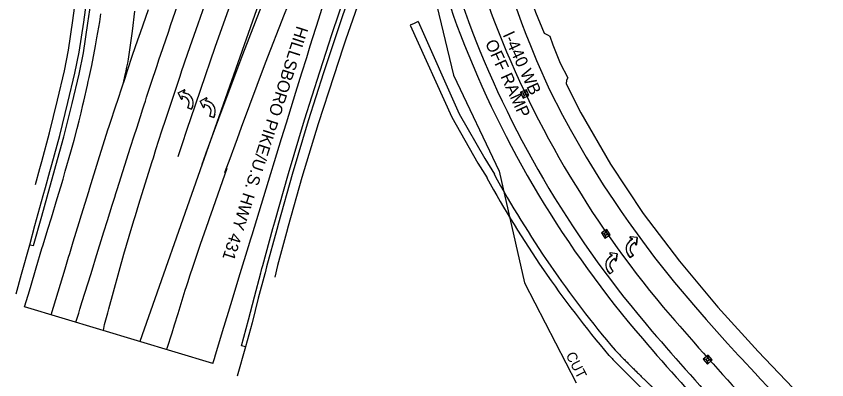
# Model space of a CAD drawing. Extents: x 1730210 to 1732101, y 650763 to 653427.
# Drawn here: x 1730314.4 to 1730714.9, y 652609 to 652788.8 of the extents above; entities that cross this region are included whole.
import ezdxf

# ---------------------------------------------------------------- set-up
doc = ezdxf.new("R2010")
doc.units = 0
for name, color, linetype in [('DESIGN - DRAINAGE - Special Ditches', 7, 'Continuous'), ('DESIGN - ROW - Slope Lines', 7, 'Continuous'), ('DESIGN - ROW - Slope Lines Text', 7, 'Continuous'), ('DESIGN - SCRATCH - User 2', 7, 'Continuous'), ('DESIGN - TRAFFIC CONTROL PERMANENT - Pavement Marking', 7, 'Continuous'), ('DESIGN - TRANSPORTATION - Edge of Traveled Way', 7, 'Continuous'), ('DESIGN - TRANSPORTATION - Intersection Lines', 7, 'Continuous'), ('DESIGN - TRANSPORTATION - Shoulder Lines', 7, 'Continuous'), ('SURVEY - DRAINAGE - Pipes and Culverts', 7, 'Continuous'), ('SURVEY - TRANSPORTATION - Features', 7, 'Continuous'), ('SURVEY - TRANSPORTATION - Roads Text', 7, 'Continuous')]:
    doc.layers.add(name, color=color, linetype=linetype)

msp = doc.modelspace()

# ---------------------------------------------------------------- linework, layer by layer
at = {"layer": 'DESIGN - DRAINAGE - Special Ditches'}
for radius in [533, 529]:
    msp.add_arc((1731014.28, 652965.13), radius, 208.7383, 220.1975, dxfattribs=at)
for points in [[(1730610.11, 652623.81), (1730622.09, 652611.66), (1730634.46, 652599.88), (1730646.95, 652588.22)], [(1730607.26, 652621), (1730619.3, 652608.79), (1730631.71, 652596.98), (1730644.22, 652585.3)]]:
    msp.add_open_spline(points, degree=2, dxfattribs=at)
at = {"layer": 'DESIGN - ROW - Slope Lines'}
for p, q in [((1730517.89, 652812.05), (1730530.41, 652759.65)), ((1730530.41, 652759.65), (1730553, 652712.18)), ((1730553, 652712.18), (1730565.43, 652657.01)), ((1730565.43, 652657.01), (1730591, 652607.46))]:
    msp.add_line(p, q, dxfattribs=at)
at = {"layer": 'DESIGN - SCRATCH - User 2'}
msp.add_lwpolyline([(1730561.33, 652793.06), (1730564.07, 652785.56), (1730566.16, 652779.94), (1730568.4, 652774.39), (1730571.4, 652766.99), (1730577.92, 652752.4), (1730584.31, 652739.97), (1730588.01, 652732.9), (1730595.99, 652719.05), (1730604.38, 652705.46), (1730609.95, 652697.18), (1730613.29, 652692.21), (1730616.72, 652687.3), (1730623.79, 652677.63), (1730629.7, 652669.58), (1730639.65, 652657.09), (1730649.97, 652644.9), (1730655.19, 652638.85), (1730664.52, 652628.44), (1730665.85, 652626.95), (1730671.28, 652621.1), (1730672.64, 652619.64), (1730679.45, 652612.34), (1730682.18, 652609.42), (1730689.03, 652602.15)], dxfattribs=at)
at = {"layer": 'DESIGN - TRAFFIC CONTROL PERMANENT - Pavement Marking'}
for p, q in [((1730454.87, 652854.32), (1730406.19, 652715.68)), ((1730394.35, 652750.93), (1730397.36, 652752.46)), ((1730394.35, 652750.93), (1730397.36, 652752.46)), ((1730397.66, 652752.08), (1730396.86, 652751.15)), ((1730396.86, 652751.15), (1730397.66, 652752.08)), ((1730396.86, 652751.15), (1730398.4, 652750.65)), ((1730398.4, 652750.65), (1730396.86, 652751.15)), ((1730395.89, 652747.92), (1730394.35, 652750.93)), ((1730394.35, 652750.93), (1730395.89, 652747.92)), ((1730397.79, 652748.78), (1730396.26, 652749.28)), ((1730396.26, 652749.28), (1730396.35, 652748.05)), ((1730397.79, 652748.78), (1730396.26, 652749.28)), ((1730396.26, 652749.28), (1730396.35, 652748.05)), ((1730405.27, 652746.88), (1730408.27, 652748.42)), ((1730405.27, 652746.88), (1730408.27, 652748.42)), ((1730408.57, 652748.04), (1730407.78, 652747.11)), ((1730407.78, 652747.11), (1730408.57, 652748.04)), ((1730407.78, 652747.11), (1730409.32, 652746.61)), ((1730409.32, 652746.61), (1730407.78, 652747.11)), ((1730399.18, 652743.47), (1730399.69, 652745.06)), ((1730399.18, 652743.47), (1730399.69, 652745.06)), ((1730401.05, 652742.86), (1730399.18, 652743.47)), ((1730399.18, 652743.47), (1730401.05, 652742.86)), ((1730401.57, 652744.46), (1730401.05, 652742.86)), ((1730401.05, 652742.86), (1730401.57, 652744.46)), ((1730406.8, 652743.88), (1730405.27, 652746.88)), ((1730405.27, 652746.88), (1730406.8, 652743.88)), ((1730408.71, 652744.74), (1730407.17, 652745.23)), ((1730407.17, 652745.23), (1730407.27, 652744.01)), ((1730408.71, 652744.74), (1730407.17, 652745.23)), ((1730407.17, 652745.23), (1730407.27, 652744.01)), ((1730410.09, 652739.43), (1730410.61, 652741.02)), ((1730410.09, 652739.43), (1730410.61, 652741.02)), ((1730411.97, 652738.82), (1730410.09, 652739.43)), ((1730410.09, 652739.43), (1730411.97, 652738.82)), ((1730412.48, 652740.41), (1730411.97, 652738.82)), ((1730411.97, 652738.82), (1730412.48, 652740.41)), ((1730406.19, 652715.68), (1730375.39, 652627.97)), ((1730617.71, 652679.28), (1730618.79, 652678.68)), ((1730618.79, 652678.68), (1730617.71, 652679.28)), ((1730621.22, 652679.35), (1730617.86, 652679.74)), ((1730621.22, 652679.35), (1730617.86, 652679.74)), ((1730620.83, 652676), (1730621.22, 652679.35)), ((1730621.22, 652679.35), (1730620.83, 652676)), ((1730618.79, 652678.68), (1730617.52, 652677.67)), ((1730617.52, 652677.67), (1730618.79, 652678.68)), ((1730618.75, 652676.13), (1730620.01, 652677.14)), ((1730618.75, 652676.13), (1730620.01, 652677.14)), ((1730620.01, 652677.14), (1730620.35, 652675.96)), ((1730620.01, 652677.14), (1730620.35, 652675.96)), ((1730607.7, 652671.31), (1730608.78, 652670.72)), ((1730608.78, 652670.72), (1730607.7, 652671.31)), ((1730611.21, 652671.39), (1730607.85, 652671.77)), ((1730611.21, 652671.39), (1730607.85, 652671.77)), ((1730610.82, 652668.03), (1730611.21, 652671.39)), ((1730611.21, 652671.39), (1730610.82, 652668.03)), ((1730619.31, 652670.67), (1730618.27, 652671.99)), ((1730619.31, 652670.67), (1730618.27, 652671.99)), ((1730608.78, 652670.72), (1730607.51, 652669.71)), ((1730607.51, 652669.71), (1730608.78, 652670.72)), ((1730608.74, 652668.17), (1730610, 652669.18)), ((1730608.74, 652668.17), (1730610, 652669.18)), ((1730610, 652669.18), (1730610.34, 652667.99)), ((1730610, 652669.18), (1730610.34, 652667.99)), ((1730616.73, 652670.76), (1730617.77, 652669.45)), ((1730617.77, 652669.45), (1730616.73, 652670.76)), ((1730617.77, 652669.45), (1730619.31, 652670.67)), ((1730619.31, 652670.67), (1730617.77, 652669.45)), ((1730609.3, 652662.71), (1730608.26, 652664.02)), ((1730609.3, 652662.71), (1730608.26, 652664.02)), ((1730606.72, 652662.8), (1730607.76, 652661.49)), ((1730607.76, 652661.49), (1730606.72, 652662.8)), ((1730607.76, 652661.49), (1730609.3, 652662.71)), ((1730609.3, 652662.71), (1730607.76, 652661.49))]:
    msp.add_line(p, q, dxfattribs=at)
for points in [[(1730383.39, 652722.85), (1730386.34, 652732.15), (1730388.22, 652737.84), (1730395.16, 652758.69), (1730396.44, 652762.47), (1730397.08, 652764.36), (1730397.72, 652766.26), (1730400.29, 652773.82), (1730404.2, 652785.15), (1730408.8, 652798.35), (1730410.17, 652802.1), (1730411.54, 652805.86), (1730412.22, 652807.74), (1730413.58, 652811.49), (1730415.63, 652817.12), (1730417, 652820.88), (1730418.42, 652824.61), (1730420.57, 652830.2), (1730422.71, 652835.8), (1730423.43, 652837.66), (1730424.86, 652841.39), (1730426.33, 652845.1), (1730433.49, 652863.11)], [(1730394.34, 652719.4), (1730396.63, 652726.34), (1730398.51, 652732.03), (1730399.14, 652733.92), (1730400.42, 652737.7), (1730405.54, 652752.84), (1730412.73, 652773.6), (1730419.37, 652792.44), (1730420.06, 652794.32), (1730422.11, 652799.95), (1730423.48, 652803.7), (1730424.84, 652807.45), (1730426.21, 652811.21), (1730426.9, 652813.08), (1730430.4, 652822.43), (1730433.3, 652829.88), (1730442.75, 652854.07), (1730444.61, 652858.82)], [(1730406.19, 652715.68), (1730406.87, 652717.55), (1730408.25, 652721.3), (1730412.37, 652732.56), (1730414.44, 652738.18), (1730426.36, 652769.97), (1730435.72, 652794.2), (1730437.19, 652797.91), (1730438.66, 652801.63), (1730439.39, 652803.49), (1730440.86, 652807.2), (1730443.07, 652812.77), (1730444.55, 652816.48), (1730446.78, 652822.05), (1730447.52, 652823.9), (1730448.26, 652825.76), (1730451.23, 652833.18), (1730452.71, 652836.89), (1730454.94, 652842.45), (1730455.69, 652844.3), (1730459.76, 652854.48)], [(1730417.45, 652711.55), (1730418.14, 652713.43), (1730419.51, 652717.18), (1730423.63, 652728.42), (1730425.69, 652734), (1730437.58, 652765.71), (1730446.9, 652789.83), (1730448.35, 652793.51), (1730449.82, 652797.22), (1730450.55, 652799.08), (1730452.01, 652802.79), (1730454.22, 652808.33), (1730455.7, 652812.03), (1730459.4, 652821.3), (1730462.37, 652828.71), (1730463.85, 652832.42), (1730466.08, 652837.98), (1730466.83, 652839.84), (1730470.16, 652848.16)], [(1730343.84, 652637.47), (1730345.25, 652642.06), (1730345.85, 652643.97), (1730347.03, 652647.79), (1730351.18, 652661.14), (1730352.36, 652664.96), (1730353.55, 652668.77), (1730357.69, 652682.13), (1730359.48, 652687.84), (1730361.86, 652695.46), (1730363.06, 652699.28), (1730363.65, 652701.18), (1730364.25, 652703.09), (1730370.84, 652724.04), (1730372.68, 652729.74), (1730373.9, 652733.54), (1730375.74, 652739.24), (1730376.96, 652743.04), (1730377.57, 652744.94), (1730378.19, 652746.84), (1730378.8, 652748.74), (1730381.86, 652758.25), (1730383.14, 652762.03), (1730383.78, 652763.92), (1730385.06, 652767.71), (1730385.7, 652769.6), (1730386.98, 652773.38), (1730388.26, 652777.16), (1730389.54, 652780.95), (1730390.82, 652784.73), (1730394.02, 652794.19)], [(1730379.6, 652791.98), (1730378.28, 652788.22), (1730375.63, 652780.68), (1730374.97, 652778.8), (1730374.32, 652776.91), (1730371.74, 652769.35), (1730369.16, 652761.79), (1730367.98, 652757.97), (1730367.41, 652756.06), (1730367.37, 652755.91)], [(1730367.37, 652755.91), (1730368.2, 652759.82), (1730368.62, 652761.77), (1730369.04, 652763.72), (1730369.45, 652765.68), (1730369.87, 652767.63), (1730371.87, 652781.47), (1730372.99, 652791.4)], [(1730318.54, 652645.09), (1730320.26, 652650.92), (1730321.41, 652654.74), (1730324.26, 652664.32), (1730327.11, 652673.89), (1730327.69, 652675.8), (1730330.01, 652683.45), (1730331.75, 652689.18), (1730334.65, 652698.74), (1730336.4, 652704.47), (1730337.51, 652708.3), (1730338.63, 652712.13), (1730341.42, 652721.72), (1730342.98, 652727.5), (1730344.51, 652733.29), (1730345.54, 652737.15), (1730346.44, 652741.04), (1730347.32, 652744.94), (1730347.77, 652746.88), (1730349.54, 652754.67), (1730349.99, 652756.62), (1730350.43, 652758.57), (1730351.76, 652764.41), (1730353.54, 652774.24), (1730354.24, 652778.17), (1730355.62, 652786.04), (1730356.22, 652789.99)], [(1730331.64, 652641.14), (1730338.49, 652663.91), (1730340.25, 652669.64), (1730340.83, 652671.55), (1730342.59, 652677.28), (1730345.51, 652686.83), (1730346.68, 652690.65), (1730348.44, 652696.37), (1730350.2, 652702.1), (1730350.8, 652704), (1730354.94, 652717.35), (1730359.68, 652732.6), (1730360.3, 652734.5), (1730360.93, 652736.4), (1730363.43, 652743.98), (1730364.68, 652747.78), (1730366.56, 652753.46), (1730367.37, 652755.91)], [(1730566.46, 652752.5), (1730563.56, 652751.26), (1730564.81, 652748.36), (1730567.71, 652749.61), (1730566.46, 652752.5)], [(1730566.46, 652752.5), (1730565.94, 652751.19), (1730564.83, 652750.71), (1730563.56, 652751.26)], [(1730567.71, 652749.61), (1730566.39, 652750.13), (1730565.29, 652749.66), (1730564.81, 652748.36)], [(1730357.46, 652633.37), (1730358.07, 652636.39), (1730359.63, 652642.17), (1730360.16, 652644.1), (1730367.51, 652671.08), (1730371.52, 652684.48), (1730372.66, 652688.31), (1730373.24, 652690.22), (1730374.95, 652695.96), (1730379.72, 652711.21), (1730381.52, 652716.92), (1730382.12, 652718.83), (1730383.38, 652722.85)], [(1730388.8, 652623.93), (1730389.03, 652624.69), (1730391.39, 652632.32), (1730392.58, 652636.14), (1730394.35, 652641.86), (1730397.91, 652653.3), (1730398.5, 652655.21), (1730399.09, 652657.12), (1730400.34, 652660.91), (1730401.63, 652664.7), (1730405.5, 652676.04), (1730409.37, 652687.38), (1730410.02, 652689.27), (1730410.66, 652691.16), (1730418.62, 652713.77)], [(1730606.17, 652683.38), (1730603.53, 652681.66), (1730605.25, 652679.02), (1730607.89, 652680.74), (1730606.17, 652683.38)], [(1730606.17, 652683.38), (1730605.88, 652682), (1730604.87, 652681.34), (1730603.53, 652681.66)], [(1730607.89, 652680.74), (1730606.51, 652681.03), (1730605.5, 652680.38), (1730605.25, 652679.02)], [(1730656.24, 652621.26), (1730653.84, 652619.22), (1730655.88, 652616.82), (1730658.28, 652618.85), (1730656.24, 652621.26)], [(1730656.24, 652621.26), (1730656.13, 652619.85), (1730655.21, 652619.07), (1730653.84, 652619.22)], [(1730658.28, 652618.85), (1730656.87, 652618.97), (1730655.96, 652618.19), (1730655.88, 652616.82)]]:
    msp.add_lwpolyline(points, dxfattribs=at)
for points in [[(1730565.94, 652751.19), (1730566.39, 652750.13), (1730565.29, 652749.66), (1730564.83, 652750.71)], [(1730605.88, 652682), (1730606.51, 652681.03), (1730605.5, 652680.38), (1730604.87, 652681.34)], [(1730656.13, 652619.85), (1730656.87, 652618.97), (1730655.96, 652618.19), (1730655.21, 652619.07)]]:
    msp.add_lwpolyline(points, close=True, dxfattribs=at)
for centre, radius, start, end in [((1730790.39, 652878.67), 257, 184.7177, 201.1154), ((1731014.28, 652965.13), 497, 201.1154, 220.7097), ((1730397.47, 652752.24), 0.246, 319.6308, 117.079), ((1730397.47, 652752.24), 0.246, 319.6308, 117.079), ((1730396.11, 652748.03), 0.246, 207.079, 4.5722), ((1730396.11, 652748.03), 0.246, 207.079, 4.5722), ((1730396.89, 652745.97), 2.95, 342.079, 72.079), ((1730396.89, 652745.97), 2.95, 342.079, 72.079), ((1730396.89, 652745.97), 4.92, 342.079, 72.079), ((1730396.89, 652745.97), 4.92, 342.079, 72.079), ((1730408.39, 652748.2), 0.246, 319.6308, 117.079), ((1730408.39, 652748.2), 0.246, 319.6308, 117.079), ((1730407.02, 652743.99), 0.246, 207.079, 4.5722), ((1730407.02, 652743.99), 0.246, 207.079, 4.5722), ((1730407.8, 652741.93), 2.95, 342.079, 72.079), ((1730407.8, 652741.93), 2.95, 342.079, 72.079), ((1730407.8, 652741.93), 4.92, 342.079, 72.079), ((1730407.8, 652741.93), 4.92, 342.079, 72.079), ((1730617.83, 652679.49), 0.246, 83.4446, 240.8929), ((1730617.83, 652679.49), 0.246, 83.4446, 240.8929), ((1730620.58, 652673.82), 4.92, 128.4446, 218.4446), ((1730620.58, 652673.82), 4.92, 128.4446, 218.4446), ((1730620.58, 652673.82), 2.95, 128.4446, 218.4446), ((1730620.58, 652673.82), 2.95, 128.4446, 218.4446), ((1730620.59, 652676.02), 0.246, 195.9514, 353.4446), ((1730620.59, 652676.02), 0.246, 195.9514, 353.4446), ((1730607.82, 652671.53), 0.246, 83.4446, 240.8929), ((1730607.82, 652671.53), 0.246, 83.4446, 240.8929), ((1730610.57, 652665.86), 4.92, 128.4446, 218.4446), ((1730610.57, 652665.86), 4.92, 128.4446, 218.4446), ((1730610.57, 652665.86), 2.95, 128.4446, 218.4446), ((1730610.57, 652665.86), 2.95, 128.4446, 218.4446), ((1730610.58, 652668.06), 0.246, 195.9514, 353.4446), ((1730610.58, 652668.06), 0.246, 195.9514, 353.4446), ((1731772.3, 653617.35), 1497, 220.70969, 225.05905)]:
    msp.add_arc(centre, radius, start, end, dxfattribs=at)
at = {"layer": 'DESIGN - TRANSPORTATION - Edge of Traveled Way'}
for points in [[(1730470.85, 652810.26), (1730463.69, 652787.38), (1730459.51, 652774.04), (1730457.72, 652768.32), (1730455.34, 652760.69), (1730452.41, 652751.14), (1730450.06, 652743.5), (1730447.71, 652735.87), (1730445.36, 652728.23), (1730436.56, 652699.59), (1730430.73, 652680.48), (1730430.15, 652678.57), (1730428.98, 652674.75), (1730424.88, 652661.38), (1730420.21, 652646.1), (1730419.05, 652642.28), (1730416.15, 652632.72), (1730413.85, 652625.07), (1730412.7, 652621.24), (1730412.13, 652619.33), (1730411.55, 652617.42), (1730411.46, 652617.1)], [(1730561.33, 652793.06), (1730564.07, 652785.56), (1730566.16, 652779.94), (1730568.4, 652774.39), (1730571.4, 652766.99), (1730577.92, 652752.4), (1730584.31, 652739.97), (1730588.01, 652732.9), (1730595.99, 652719.05), (1730604.38, 652705.46), (1730609.95, 652697.18), (1730613.29, 652692.21), (1730616.72, 652687.3), (1730623.79, 652677.63), (1730629.7, 652669.58), (1730639.65, 652657.09), (1730649.97, 652644.9), (1730655.19, 652638.85), (1730664.52, 652628.44), (1730665.85, 652626.95), (1730671.28, 652621.1), (1730672.64, 652619.64), (1730679.45, 652612.34), (1730682.18, 652609.42), (1730689.03, 652602.15)]]:
    msp.add_lwpolyline(points, dxfattribs=at)
for centre, radius, start, end in [((1730790.39, 652878.67), 269, 184.7177, 201.1154), ((1731014.28, 652965.13), 509, 201.1154, 220.7097), ((1731772.3, 653617.35), 1509, 220.70969, 225.05905)]:
    msp.add_arc(centre, radius, start, end, dxfattribs=at)
at = {"layer": 'DESIGN - TRANSPORTATION - Intersection Lines'}
msp.add_line((1730411.46, 652617.1), (1730318.54, 652645.09), dxfattribs=at)
at = {"layer": 'DESIGN - TRANSPORTATION - Shoulder Lines'}
for centre, radius, start, end in [((1730790.39, 652878.67), 275, 184.7177, 201.1154), ((1731014.28, 652965.13), 515, 201.1154, 220.7097), ((1731772.3, 653617.35), 1515, 220.70969, 225.05905)]:
    msp.add_arc(centre, radius, start, end, dxfattribs=at)
at = {"layer": 'SURVEY - DRAINAGE - Pipes and Culverts'}
for points in [[(1730512.9, 652786.18), (1730510.92, 652785.24), (1730509.01, 652784.33), (1730529.57, 652738.9), (1730542.51, 652716.13), (1730547.06, 652708.94)], [(1730512.9, 652786.18), (1730533.24, 652740.64), (1730545.87, 652718.42), (1730550.69, 652710.79)]]:
    msp.add_lwpolyline(points, dxfattribs=at)
at = {"layer": 'SURVEY - TRANSPORTATION - Features'}
for p, q in [((1730576.8, 652779.63), (1730578.1, 652779.03)), ((1730586.93, 652758.33), (1730586.18, 652757.16))]:
    msp.add_line(p, q, dxfattribs=at)
for points in [[(1730508.48, 652880.76), (1730505, 652871.87), (1730496.11, 652848.62), (1730487.95, 652825.93), (1730480, 652802.33), (1730472.07, 652778.64), (1730470.91, 652775.13), (1730466.22, 652760.83), (1730458.62, 652737.08), (1730450.72, 652710.55), (1730443.99, 652686.52), (1730443.09, 652683.31), (1730438.07, 652664.91), (1730437.67, 652663.46), (1730437.3, 652661.97), (1730437.15, 652661.4), (1730433.98, 652649.41), (1730430.87, 652637.21), (1730427.62, 652625.31), (1730423.53, 652610.75)], [(1730427.62, 652625.31), (1730425.73, 652625.88), (1730429.12, 652638.63), (1730432.09, 652649.99), (1730435.24, 652661.98), (1730435.39, 652662.56), (1730435.76, 652664.05), (1730436.16, 652665.49), (1730441.19, 652683.89), (1730442.07, 652687.1), (1730448.86, 652711.12), (1730456.77, 652737.65), (1730464.36, 652761.41), (1730469, 652775.72), (1730470.15, 652779.25), (1730478.09, 652802.93), (1730486.18, 652826.5), (1730494.38, 652849.31), (1730503.25, 652872.58), (1730506.72, 652881.42)], [(1730337.98, 652729.24), (1730342.02, 652745.63), (1730345.43, 652760.21), (1730347.56, 652770.69), (1730349.84, 652785.47), (1730351.17, 652795.26), (1730351.85, 652801.9), (1730352.26, 652805.29), (1730353.73, 652820.11), (1730354.38, 652834.8), (1730354.26, 652849.28), (1730354.32, 652859.54), (1730354.37, 652861.87), (1730352.6, 652861.75)], [(1730554.83, 652857.03), (1730557.5, 652839.27), (1730559.67, 652827.99), (1730562.4, 652816.32), (1730566.77, 652802.56), (1730571, 652790.87), (1730575.24, 652780.51), (1730576.8, 652779.63)], [(1730503.59, 652852.7), (1730501.24, 652846.56), (1730493.25, 652824.26), (1730485.31, 652800.68), (1730477.11, 652777.06), (1730475.91, 652773.56), (1730471.22, 652759.27), (1730463.62, 652735.54), (1730455.47, 652709.09), (1730448.75, 652685.07), (1730447.85, 652681.86)], [(1730323.87, 652705.55), (1730326.04, 652713.45), (1730327.06, 652716.97), (1730330.81, 652731.15), (1730334.78, 652747.28), (1730338.17, 652761.86), (1730340.23, 652772.01), (1730342.4, 652786.78), (1730343.71, 652796.4), (1730344.43, 652802.74), (1730349.2, 652802.2)], [(1730314.37, 652651.55), (1730317.03, 652661.21), (1730321.04, 652675.83), (1730323.65, 652685.33), (1730327.77, 652700.22), (1730328.82, 652704.05), (1730331.03, 652712), (1730332.04, 652715.52), (1730335.89, 652729.8), (1730339.91, 652746.11), (1730343.31, 652760.69), (1730345.43, 652771.07), (1730347.71, 652785.85), (1730349.04, 652795.59)], [(1730578.1, 652779.03), (1730579.52, 652774.66), (1730583.16, 652765.57), (1730586.93, 652758.33)], [(1730586.18, 652757.16), (1730586.11, 652755.47), (1730593.26, 652741.04), (1730607.98, 652715.66), (1730624.18, 652691.26), (1730642.02, 652667.64), (1730661.04, 652644.94), (1730680.98, 652623.04), (1730701.46, 652601.45)], [(1730321.04, 652675.83), (1730322.96, 652675.41), (1730326.95, 652689.87), (1730331.01, 652704.29), (1730333.01, 652711.42), (1730333.99, 652714.95), (1730337.98, 652729.24)], [(1730447.85, 652681.86), (1730443.42, 652665.49), (1730442.21, 652659.85)]]:
    msp.add_lwpolyline(points, dxfattribs=at)

# ---------------------------------------------------------------- texts
at = {"layer": 'DESIGN - ROW - Slope Lines Text'}
msp.add_text('CUT', height=5, rotation=297.3022, dxfattribs=at).set_placement((1730585.75, 652621.26))
at = {"layer": 'SURVEY - TRANSPORTATION - Roads Text'}
for s, rotation, p in [('HILLSBORO PIKE/U.S. HWY 431', 252.2463, (1730453.02, 652784.37)), ('I-440 WB', 294.6224, (1730554.62, 652779.69)), ('OFF RAMP', 294.6224, (1730545.89, 652775.69))]:
    msp.add_text(s, height=6, rotation=rotation, dxfattribs=at).set_placement(p)

doc.saveas('drawing.dxf')
